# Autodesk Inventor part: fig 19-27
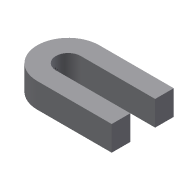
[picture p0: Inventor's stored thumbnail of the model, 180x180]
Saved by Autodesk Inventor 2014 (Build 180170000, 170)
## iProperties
Created: 2013-07
Part Number: fig 19-27
Material: Generic
Document SubType Name: Modeling
Designer: CADCIM
Density: 1 g/cm^3
Appearance: Default
Author: CADCIM
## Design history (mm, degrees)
sketch "Sketch1"
  geometry: L1 (0, 12.5)-(30, 12.5); L2 (0, -12.5)-(30, -12.5); L3 (30, -12.5)-(30, -5); L4 (30, -5)-(0, -5); L5 (30, 12.5)-(30, 5); L6 (30, 5)-(0, 5); A1 r 12.5 centre (0, 0) between (0, 12.5) and (0, -12.5); A2 r 5 centre (0, 0) between (0, 5) and (0, -5); 1 further point
  constraints: 12 end point, 4 point on circle, 3 perpendicular, 2 centre point, 2 coincident, 2 parallel, 2 tangent, 1 horizontal
  dimensions: "d3" = 7.5 distance of L2.end L3.end; "d4" = 7.5 distance of L1.end L5.end
extrude "Extrusion1" new body sketch "Sketch1" distance "d5" = 10; taper "d6" = 0 deg
workplane "Work Plane1"
sketch "Sketch2"
  geometry: 2 further points
body "Solid1"
other parameters: "d7" = -35
